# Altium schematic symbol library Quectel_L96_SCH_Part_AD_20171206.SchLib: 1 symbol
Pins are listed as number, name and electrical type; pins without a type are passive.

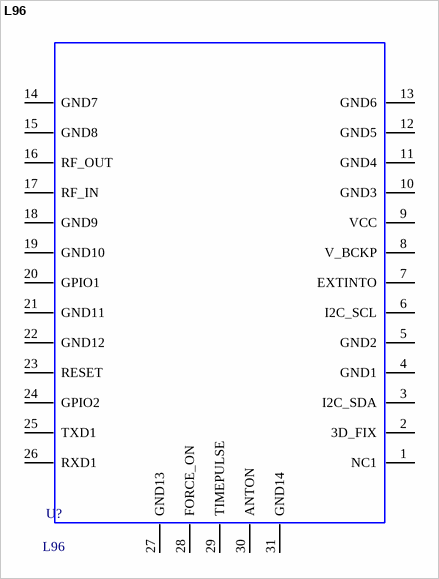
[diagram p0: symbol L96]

## L96
designator U?
Part Description: MODULE L96 31pin 14.0x9.6mm RO; Manufacturer: QUECTEL
pins: 1 NC1, 2 3D_FIX, 3 I2C_SDA, 4 GND1, 5 GND2, 6 I2C_SCL, 7 EXTINTO, 8 V_BCKP, 9 VCC, 10 GND3, 11 GND4, 12 GND5, 13 GND6, 14 GND7, 15 GND8, 16 RF_OUT, 17 RF_IN, 18 GND9, 19 GND10, 20 GPIO1, 21 GND11, 22 GND12, 23 RESET, 24 GPIO2, 25 TXD1, 26 RXD1, 27 GND13, 28 FORCE_ON, 29 TIMEPULSE, 30 ANTON, 31 GND14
